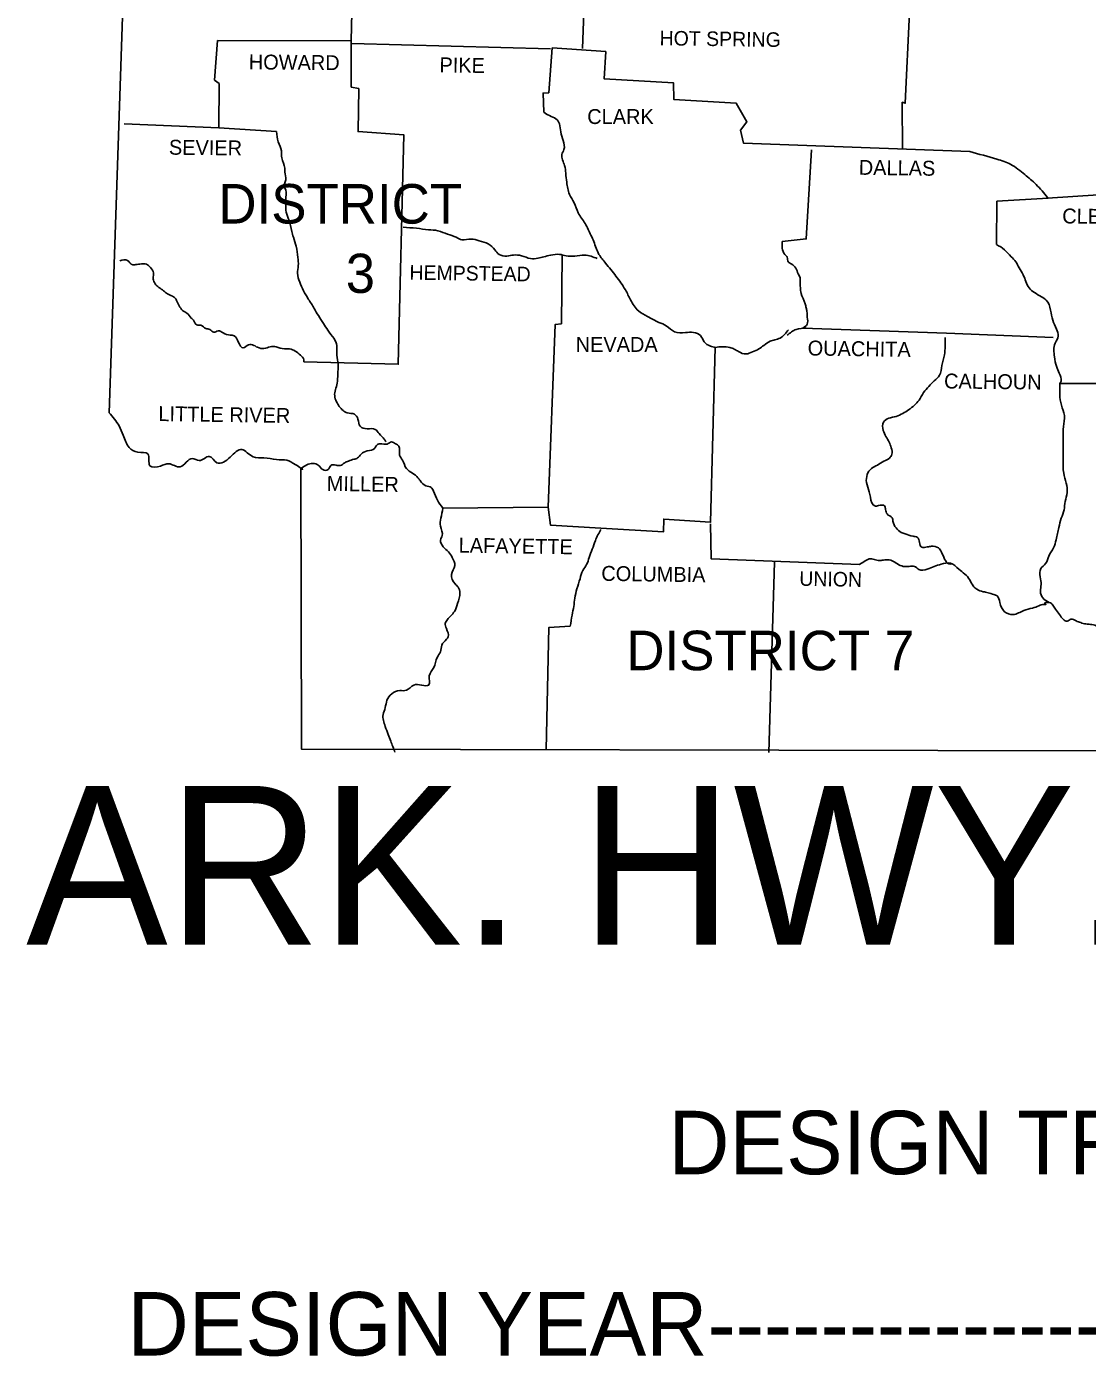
# Model space of a CAD drawing. Extents: x 309348 to 309445, y 336383 to 336484.
# Drawn here: x 309372.861 to 309375.728, y 336395.614 to 336399.208 of the extents above; entities that cross this region are included whole.
import ezdxf

# ---------------------------------------------------------------- set-up
doc = ezdxf.new("R2010")
doc.units = 0
doc.layers.add('R_Annotation', color=7, linetype='Continuous')

msp = doc.modelspace()

# ---------------------------------------------------------------- linework, layer by layer
at = {"layer": 'R_Annotation'}
for points in [[(309372.9764, 336402.2658), (309373.1698, 336400.7078), (309373.0841, 336398.1647)], [(309374.3854, 336399.7333), (309374.3635, 336399.1493)], [(309373.7492, 336399.6304), (309373.7386, 336399.1693), (309373.3774, 336399.1704), (309373.3689, 336399.0635), (309373.382, 336399.0541), (309373.381, 336398.9341), (309373.1248, 336398.9455)], [(309375.2475, 336399.2464), (309375.2361, 336399.0008), (309375.2277, 336399.0036), (309375.2286, 336398.8761)], [(309373.7386, 336399.1693), (309373.7386, 336399.0446), (309373.7592, 336399.0408), (309373.7573, 336398.9246), (309373.8811, 336398.9152), (309373.8658, 336398.2956), (309373.6106, 336398.3022)], [(309373.7405, 336399.1627), (309374.2772, 336399.1484)], [(309374.2593, 336398.9769), (309374.2574, 336399.0284), (309374.2725, 336399.0293), (309374.2819, 336399.1503), (309374.4264, 336399.1408), (309374.4226, 336399.0668), (309374.6093, 336399.0564), (309374.6103, 336399.0114), (309374.7792, 336399.001), (309374.8082, 336398.9504), (309374.7904, 336398.9279), (309374.7988, 336398.8932), (309375.4106, 336398.8704)], [(309373.381, 336398.9341), (309373.5367, 336398.9247)], [(309374.9827, 336398.8753), (309374.9685, 336398.6344), (309374.9038, 336398.6269)], [(309375.7577, 336398.7531), (309375.6207, 336398.7447)], [(309375.6226, 336398.7447), (309375.4837, 336398.7363), (309375.4827, 336398.6192)], [(309374.3088, 336398.5916), (309374.3069, 336398.405), (309374.29, 336398.4032), (309374.2709, 336397.9092)], [(309374.959, 336398.3935), (309375.3475, 336398.3792), (309375.6355, 336398.3679)], [(309374.7225, 336398.3411), (309374.7101, 336397.8687), (309374.5834, 336397.8772), (309374.5824, 336397.8425), (309374.4135, 336397.8529)], [(309375.6542, 336398.2432), (309376.0784, 336398.2439)], [(309373.6029, 336398.0135), (309373.6044, 336397.2552), (309377.0434, 336397.248)], [(309374.4135, 336397.8529), (309374.2775, 336397.8604), (309374.2709, 336397.9092), (309373.9866, 336397.9065)], [(309375.1126, 336397.7541), (309374.7119, 336397.7693), (309374.7101, 336397.864)], [(309374.8827, 336397.7608), (309374.8674, 336397.2462)], [(309374.3308, 336397.5876), (309374.2727, 336397.5839), (309374.2659, 336397.254)]]:
    msp.add_lwpolyline(points, dxfattribs=at)
for points in [[(309374.2593, 336398.9769), (309374.2743, 336398.9675), (309374.2921, 336398.959), (309374.3015, 336398.945), (309374.3052, 336398.9234), (309374.3118, 336398.9), (309374.3137, 336398.8756), (309374.308, 336398.8625), (309374.3155, 336398.8325), (309374.3183, 336398.8118), (309374.3211, 336398.7875), (309374.3286, 336398.7547), (309374.3408, 336398.7322), (309374.3521, 336398.705), (309374.3708, 336398.6759), (309374.3867, 336398.644), (309374.3942, 336398.6272), (309374.4083, 336398.5925), (309374.4261, 336398.569), (309374.4542, 336398.5334), (309374.4796, 336398.4968), (309374.4936, 336398.4696), (309374.5152, 336398.4396), (309374.5396, 336398.4246), (309374.5705, 336398.4087), (309374.5902, 336398.3993), (309374.6127, 336398.3833), (309374.6418, 336398.3814), (309374.6634, 336398.3814), (309374.6831, 336398.373), (309374.6925, 336398.3561), (309374.7094, 336398.3449), (309374.7225, 336398.3411)], [(309373.5367, 336398.9247), (309373.5414, 336398.8966), (309373.5499, 336398.8722), (309373.5508, 336398.8534), (309373.5592, 336398.8253), (309373.5592, 336398.815), (309373.562, 336398.7944), (309373.5583, 336398.7831), (309373.5629, 336398.7606), (309373.562, 336398.7438), (309373.562, 336398.7297), (309373.5629, 336398.7063), (309373.5704, 336398.6856), (309373.5779, 336398.6547), (309373.5826, 336398.6388), (309373.5901, 336398.6144), (309373.5947, 336398.5844), (309373.5957, 336398.5619), (309373.5938, 336398.5413), (309373.5994, 336398.5178), (309373.6097, 336398.4944), (309373.6228, 336398.4719), (309373.6388, 336398.4466), (309373.65, 336398.4269), (309373.6641, 336398.4053), (309373.6753, 336398.3875), (309373.6922, 336398.365), (309373.6997, 336398.3463), (309373.6997, 336398.32), (309373.7034, 336398.2956), (309373.7025, 336398.2685), (309373.7006, 336398.2441), (309373.694, 336398.2103), (309373.6987, 336398.1944), (309373.7165, 336398.171), (309373.7278, 336398.1644), (309373.7475, 336398.1606), (309373.7569, 336398.1475), (309373.7625, 336398.1278), (309373.7822, 336398.1212), (309373.8038, 336398.1194), (309373.8141, 336398.1081), (309373.8281, 336398.0931), (309373.8328, 336398.0856)], [(309375.4106, 336398.8704), (309375.4838, 336398.8497), (309375.5213, 336398.8357), (309375.5588, 336398.8085), (309375.5898, 336398.7813), (309375.6207, 336398.7466)], [(309373.8791, 336398.6658), (309373.9148, 336398.663), (309373.9476, 336398.6592), (309373.9729, 336398.6564), (309373.9992, 336398.647), (309374.0227, 336398.6386), (309374.0377, 336398.632), (309374.063, 336398.6339), (309374.0846, 336398.6292), (309374.109, 336398.6207), (309374.1268, 336398.6048), (309374.1381, 336398.5926), (309374.1596, 336398.5879), (309374.1775, 336398.5907), (309374.199, 336398.5888), (309374.2234, 336398.5813), (309374.2431, 336398.5822), (309374.2591, 336398.586), (309374.2779, 336398.5906), (309374.3013, 336398.5925), (309374.3192, 336398.5888), (309374.3426, 336398.5878), (309374.3698, 336398.5906), (309374.4036, 336398.5812)], [(309374.9038, 336398.6269), (309374.9038, 336398.6091), (309374.9103, 336398.5922), (309374.9169, 336398.5847), (309374.9197, 336398.5725), (309374.9281, 336398.5669), (309374.9403, 336398.5557), (309374.9469, 336398.5397), (309374.9516, 336398.5294), (309374.9516, 336398.5163), (309374.9525, 336398.5032), (309374.9544, 336398.4872), (309374.9656, 336398.4591), (309374.9684, 336398.4478), (309374.9703, 336398.4385), (309374.9712, 336398.4225), (309374.9712, 336398.4038), (309374.959, 336398.3935)], [(309375.4827, 336398.6192), (309375.5043, 336398.6051), (309375.5221, 336398.5863), (309375.5352, 336398.5723), (309375.5437, 336398.5563), (309375.5549, 336398.5376), (309375.5709, 336398.5019), (309375.5849, 336398.4897), (309375.6046, 336398.4776), (309375.6168, 336398.4691), (309375.629, 336398.4419), (309375.6346, 336398.4147), (309375.6449, 336398.3904), (309375.6496, 336398.3716), (309375.6412, 336398.3529), (309375.6393, 336398.3154), (309375.6449, 336398.2901), (309375.6524, 336398.2713), (309375.6571, 336398.2497), (309375.6542, 336398.2432)], [(309373.1134, 336398.5752), (309373.134, 336398.5762), (309373.1481, 336398.564), (309373.1565, 336398.5649), (309373.1715, 336398.5668), (309373.1856, 336398.5658), (309373.1959, 336398.5574), (309373.2044, 336398.5424), (309373.2034, 336398.5283), (309373.2044, 336398.5227), (309373.2109, 336398.5105), (309373.2222, 336398.5011), (309373.2344, 336398.4918), (309373.2456, 336398.4843), (309373.2644, 336398.4721), (309373.2663, 336398.4683), (309373.2738, 336398.4533), (309373.2831, 336398.4411), (309373.2944, 336398.4336), (309373.3066, 336398.4205), (309373.3122, 336398.4149), (309373.3216, 336398.4017), (309373.3319, 336398.4008), (309373.346, 336398.3923), (309373.3563, 336398.3895), (309373.3676, 336398.382), (309373.3788, 336398.3858), (309373.3929, 336398.3801), (309373.4117, 336398.3745), (309373.422, 336398.3726), (309373.4342, 336398.3548), (309373.4464, 336398.3398), (309373.4614, 336398.3482), (309373.4895, 336398.3398), (309373.5074, 336398.3388), (309373.5233, 336398.3435), (309373.5355, 336398.3426), (309373.558, 336398.3369), (309373.5721, 336398.3369), (309373.5871, 336398.3313), (309373.6012, 336398.3201), (309373.6106, 336398.3079), (309373.6106, 336398.3022)], [(309374.9168, 336398.3738), (309374.9412, 336398.3897), (309374.9684, 336398.3935)], [(309374.9205, 336398.3888), (309374.9102, 336398.3766), (309374.898, 336398.3663), (309374.8839, 336398.3616), (309374.8708, 336398.3579), (309374.8539, 336398.3467), (309374.8407, 336398.3373), (309374.8229, 336398.3289), (309374.806, 336398.3233), (309374.7854, 336398.3298), (309374.7741, 336398.3364), (309374.7619, 336398.3411), (309374.7225, 336398.3411)], [(309375.3437, 336398.368), (309375.3418, 336398.3211), (309375.3352, 336398.2921), (309375.3286, 336398.2658), (309375.3146, 336398.2508), (309375.2995, 336398.2359), (309375.2855, 336398.219), (309375.2732, 336398.1984), (309375.261, 336398.1852), (309375.2451, 336398.1721), (309375.2291, 336398.1628), (309375.2113, 336398.1543), (309375.1916, 336398.1497), (309375.1775, 336398.1394), (309375.1766, 336398.1169), (309375.1925, 336398.085), (309375.1981, 336398.07), (309375.2, 336398.0522), (309375.1934, 336398.0419), (309375.1784, 336398.0334), (309375.1606, 336398.0231), (309375.1446, 336398.0138), (309375.1333, 336397.9978), (309375.1314, 336397.9763), (309375.1389, 336397.951), (309375.1417, 336397.936), (309375.1539, 336397.9125), (309375.1633, 336397.9135), (309375.1802, 336397.9125), (309375.1821, 336397.9078), (309375.183, 336397.9031), (309375.1868, 336397.8909), (309375.2008, 336397.8806), (309375.2027, 336397.8713), (309375.2111, 336397.8534), (309375.2252, 336397.8412), (309375.2355, 336397.8375), (309375.2571, 336397.8309), (309375.2684, 336397.8281), (309375.2806, 336397.8009), (309375.2956, 336397.8018), (309375.3068, 336397.8037), (309375.3256, 336397.799), (309375.334, 336397.7878), (309375.3425, 336397.769), (309375.3537, 336397.7559), (309375.3612, 336397.7559)], [(309375.6542, 336398.2432), (309375.658, 336398.1851), (309375.6664, 336398.1569), (309375.6636, 336398.1269), (309375.6626, 336398.0979), (309375.6626, 336398.0716), (309375.6626, 336398.0463), (309375.6626, 336398.0201), (309375.6644, 336398.0013), (309375.671, 336397.9742), (309375.6738, 336397.9488), (309375.6682, 336397.9245), (309375.6653, 336397.902), (309375.6578, 336397.8795), (309375.6512, 336397.8542), (309375.6437, 336397.8214), (309375.6371, 336397.7998), (309375.624, 336397.7773), (309375.6155, 336397.7567), (309375.6024, 336397.7436), (309375.6005, 336397.7211), (309375.6033, 336397.7005), (309375.6014, 336397.6817), (309375.608, 336397.6639), (309375.6248, 336397.6517)], [(309373.0841, 336398.1647), (309373.1113, 336398.1291), (309373.1225, 336398.1037), (309373.1384, 336398.0709), (309373.1619, 336398.0578), (309373.1891, 336398.0531), (309373.1947, 336398.0212), (309373.2229, 336398.0203), (309373.2454, 336398.0268), (309373.2764, 336398.0184), (309373.3092, 336398.0408), (309373.328, 336398.0352), (309373.3552, 336398.0465), (309373.3758, 336398.0296), (309373.4115, 336398.0446), (309373.4434, 336398.0652), (309373.4734, 336398.0455), (309373.5025, 336398.0426), (309373.5372, 336398.0379), (309373.5644, 336398.036), (309373.5888, 336398.0238), (309373.6067, 336398.0117), (309373.6029, 336398.0135)], [(309373.6029, 336398.0135), (309373.6357, 336398.0276), (309373.6498, 336398.0229), (309373.662, 336398.0107), (309373.6761, 336398.0107), (309373.6836, 336398.0219), (309373.6977, 336398.0229), (309373.7089, 336398.0219), (309373.7211, 336398.0294), (309373.7315, 336398.0341), (309373.7455, 336398.0388), (309373.7559, 336398.0425), (309373.7653, 336398.0528), (309373.7821, 336398.0613), (309373.8019, 336398.0678), (309373.8075, 336398.0772), (309373.8169, 336398.0809), (309373.8356, 336398.08), (309373.8478, 336398.0856), (309373.8582, 336398.0809), (309373.8675, 336398.0743), (309373.8694, 336398.05), (309373.8769, 336398.0368), (309373.8882, 336398.0134), (309373.9041, 336398.0012), (309373.9191, 336397.989), (309373.9247, 336397.9815), (309373.9407, 336397.9674), (309373.9548, 336397.9628), (309373.9613, 336397.9524), (309373.9716, 336397.9281), (309373.9866, 336397.9065)], [(309373.9866, 336397.9065), (309373.981, 336397.8793), (309373.98, 336397.8578), (309373.9847, 336397.8324), (309373.98, 336397.8203), (309373.9875, 336397.8024), (309374.0016, 336397.7884), (309374.0119, 336397.7734), (309374.0185, 336397.7518), (309374.01, 336397.7274), (309374.0194, 336397.7021), (309374.0278, 336397.6928), (309374.0325, 336397.6778), (309374.0259, 336397.6487), (309374.0175, 336397.6271), (309373.9987, 336397.6056), (309373.993, 336397.5953), (309373.9958, 336397.5812), (309374.0005, 336397.5587), (309373.9958, 336397.5522), (309373.9836, 336397.5362), (309373.9799, 336397.5184), (309373.9714, 336397.5034), (309373.962, 336397.4762), (309373.9498, 336397.4538), (309373.9479, 336397.4284), (309373.9291, 336397.4285), (309373.9076, 336397.4285), (309373.8878, 336397.4144), (309373.87, 336397.4135), (309373.8484, 336397.4051), (309373.8353, 336397.3873), (309373.8306, 336397.3676), (309373.8249, 336397.3488), (309373.8306, 336397.317), (309373.839, 336397.2945), (309373.8456, 336397.2766), (309373.8568, 336397.2476)], [(309374.3308, 336397.5876), (309374.3355, 336397.6176), (309374.3402, 336397.6411), (309374.3431, 336397.6636), (309374.3487, 336397.6889), (309374.3572, 336397.716), (309374.3647, 336397.7385), (309374.375, 336397.7545), (309374.3816, 336397.7732), (309374.3901, 336397.7957), (309374.3985, 336397.8191), (309374.4135, 336397.8491)], [(309375.1126, 336397.7541), (309375.1276, 336397.7644), (309375.1417, 336397.77), (309375.1557, 336397.7672), (309375.1707, 336397.7653), (309375.1839, 336397.7672), (309375.2008, 336397.7644), (309375.2148, 336397.756), (309375.2308, 336397.7494), (309375.2467, 336397.7494), (309375.2608, 336397.7494), (309375.273, 336397.7409), (309375.2955, 336397.7419), (309375.3143, 336397.7493), (309375.3331, 336397.755), (309375.3584, 336397.7578), (309375.3809, 336397.7418), (309375.3969, 336397.7287), (309375.41, 336397.7137), (309375.4194, 336397.6968), (309375.4297, 336397.6874), (309375.4466, 336397.6809), (309375.4597, 336397.678), (309375.4757, 336397.6733), (309375.4841, 336397.6696), (309375.4916, 336397.6518), (309375.5038, 336397.6274), (309375.5272, 336397.619), (309375.5563, 336397.6302), (309375.5798, 336397.6367), (309375.5967, 336397.6424), (309375.607, 336397.6461), (309375.6164, 336397.647), (309375.6136, 336397.6489), (309375.6248, 336397.6517), (309375.6352, 336397.6442), (309375.6417, 336397.6339), (309375.653, 336397.6189), (309375.6633, 336397.6058), (309375.6736, 336397.6011), (309375.6839, 336397.6067), (309375.698, 336397.602), (309375.7102, 336397.5973), (309375.7243, 336397.5936), (309375.7365, 336397.5926), (309375.7524, 336397.5889), (309375.7646, 336397.5823), (309375.7759, 336397.5757), (309375.7871, 336397.5635), (309375.7984, 336397.5448), (309375.8021, 336397.5298), (309375.8153, 336397.5148), (309375.8275, 336397.5148), (309375.8453, 336397.4904), (309375.8518, 336397.481), (309375.8659, 336397.4641), (309375.8762, 336397.4641), (309375.8959, 336397.4604)]]:
    msp.add_spline(points, degree=3, dxfattribs=at)

# ---------------------------------------------------------------- texts
for s, height, rotation, p in [('HOT SPRING', 0.03937, 359.1962, (309374.5719, 336399.1576)), ('HOWARD', 0.04031, 359.4887, (309373.4618, 336399.0925)), ('PIKE', 0.0403, 359.0199, (309373.9769, 336399.0848)), ('CLARK', 0.04031, 359.9738, (309374.3766, 336398.9449)), ('SEVIER', 0.04031, 359.4014, (309373.2458, 336398.862)), ('DALLAS', 0.0403, 359.2207, (309375.1103, 336398.8077)), ('DISTRICT', 0.10686, 359.9738, (309373.3796, 336398.6759)), ('CLEVELAND', 0.04031, 359.3121, (309375.6601, 336398.6763)), ('3', 0.1059, 359.9738, (309373.7241, 336398.4884)), ('HEMPSTEAD', 0.03936, 359.1631, (309373.8959, 336398.5243)), ('NEVADA', 0.04031, 359.9738, (309374.3453, 336398.3291)), ('OUACHITA', 0.04031, 359.1789, (309374.9721, 336398.3194)), ('CALHOUN', 0.04031, 359.3378, (309375.3408, 336398.2302)), ('LITTLE RIVER', 0.040309, 359.1443, (309373.2173, 336398.1421)), ('MILLER', 0.0403, 359.1066, (309373.6723, 336397.9535)), ('LAFAYETTE', 0.0403, 359.1585, (309374.0288, 336397.7865)), ('COLUMBIA', 0.0403, 359.1871, (309374.4144, 336397.7104)), ('UNION', 0.03937, 358.9332, (309374.9493, 336397.697)), ('DISTRICT 7', 0.10686, 359.9738, (309374.4821, 336397.4687))]:
    msp.add_text(s, height=height, rotation=rotation, dxfattribs=at).set_placement(p)
for s, height, p in [('ARK. HWY. DIST. NO. 10', 0.428716, (309372.8603, 336396.7273)), ('DESIGN TRAFFIC DATA', 0.171486, (309374.5955, 336396.1065)), ('DESIGN YEAR-----------------------', 0.171486, (309373.1341, 336395.6166))]:
    msp.add_text(s, height=height, dxfattribs=at).set_placement(p)

doc.saveas('drawing.dxf')
